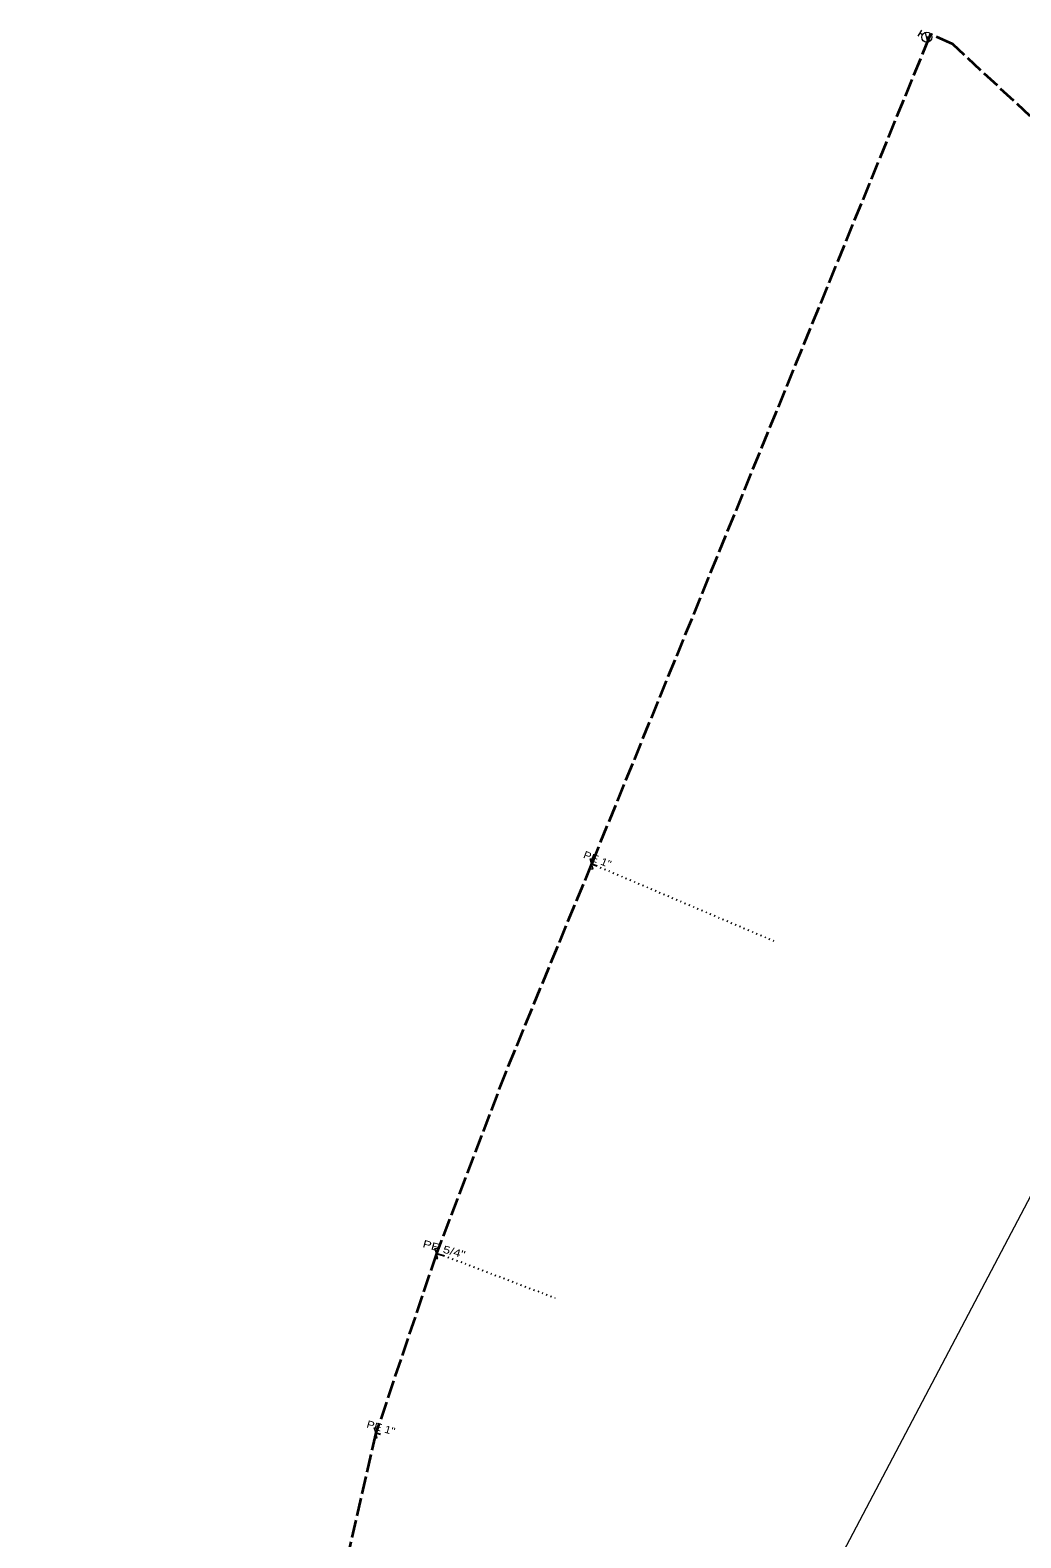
# Model space of a CAD drawing. Extents: x -582626 to -580899, y -1097611 to -1096610.
# Drawn here: x -581490.3 to -581390.7, y -1096761 to -1096609.6 of the extents above; entities that cross this region are included whole.
import ezdxf
from ezdxf.enums import TextEntityAlignment as Align

# ---------------------------------------------------------------- set-up
doc = ezdxf.new("R2010")
doc.units = 0
doc.header["$LTSCALE"] = 0.3
doc.linetypes.add('DOTTED', pattern=[1.5, 0.3, -1.2])
doc.linetypes.add('LONG_DASHED', pattern=[7.5, 6, -1.5])
for name, color, linetype, lineweight in [('1', 7, 'Continuous', 13), ('10', 7, 'Continuous', 13), ('35', 7, 'LONG_DASHED', 35), ('50', 7, 'LONG_DASHED', 25), ('51', 7, 'DOTTED', 25)]:
    doc.layers.add(name, color=color, linetype=linetype, lineweight=lineweight)
doc.layers.add('19', color=7, linetype='Continuous')

msp = doc.modelspace()

# ---------------------------------------------------------------- linework, layer by layer
at = {"layer": '1'}
msp.add_lwpolyline([(-582625.57, -1097394.66), (-582612.34, -1097467.421), (-582321.299, -1097262.369), (-581897.965, -1097202.837), (-581719.372, -1097182.994), (-581593.695, -1097110.233), (-581382.028, -1096971.327), (-581362.184, -1096819.192), (-581322.497, -1096739.817), (-581210.049, -1096733.202), (-581097.601, -1096686.9), (-580905.778, -1096719.973), (-580899.163, -1096627.369), (-581084.372, -1096614.14), (-581216.663, -1096680.285), (-581368.799, -1096686.9), (-581434.945, -1096812.577), (-581468.018, -1096971.327), (-581659.84, -1097004.4), (-581831.82, -1097110.233), (-582314.684, -1097169.765), (-582519.736, -1097295.442), (-582625.57, -1097394.66)], close=True, dxfattribs=at)
at = {"layer": '10'}
for p, q in [((-581401.014, -1096610.197), (-581400.652, -1096609.598)), ((-581400.576, -1096610.052), (-581400.833, -1096609.897)), ((-581400.028, -1096610.797), (-581400.268, -1096609.826))]:
    msp.add_line(p, q, dxfattribs=at)
for points in [[(-581433.835, -1096693.326), (-581433.985, -1096692.826), (-581433.685, -1096692.826), (-581433.835, -1096693.326), (-581433.985, -1096693.826), (-581433.685, -1096693.826)], [(-581449.419, -1096732.464), (-581449.569, -1096731.964), (-581449.269, -1096731.964), (-581449.419, -1096732.464), (-581449.569, -1096732.964), (-581449.269, -1096732.964)], [(-581455.523, -1096750.461), (-581455.673, -1096749.961), (-581455.373, -1096749.961), (-581455.523, -1096750.461), (-581455.673, -1096750.961), (-581455.373, -1096750.961)]]:
    msp.add_lwpolyline(points, close=True, dxfattribs=at)
msp.add_circle((-581400.1481, -1096610.3107), 0.5, dxfattribs=at)
at = {"layer": '35'}
msp.add_line((-581400.148, -1096610.311), (-581399.945, -1096610.388), dxfattribs=at)
for points in [[(-581399.786, -1096610.001), (-581399.945, -1096610.388), (-581433.835, -1096693.326)], [(-581338.976, -1096669.3), (-581341.123, -1096666.369), (-581373.277, -1096633.554), (-581397.534, -1096611.01), (-581399.786, -1096610.001)], [(-581433.835, -1096693.326), (-581442.496, -1096714.31), (-581449.419, -1096732.464)], [(-581449.419, -1096732.464), (-581455.402, -1096750.202), (-581455.523, -1096750.461)], [(-581455.523, -1096750.461), (-581465.398, -1096793.715), (-581467.375, -1096804.966), (-581469.14, -1096820.168), (-581469.913, -1096823.394)]]:
    msp.add_lwpolyline(points, dxfattribs=at)
at = {"layer": '50'}
for p, q in [((-581433.835, -1096693.326), (-581433.38, -1096693.503)), ((-581449.419, -1096732.464), (-581448.699, -1096732.662)), ((-581455.523, -1096750.461), (-581455.05, -1096750.596))]:
    msp.add_line(p, q, dxfattribs=at)
at = {"layer": '51'}
for p, q in [((-581433.38, -1096693.503), (-581415.534, -1096701.055)), ((-581448.699, -1096732.662), (-581437.508, -1096736.922))]:
    msp.add_line(p, q, dxfattribs=at)

# ---------------------------------------------------------------- texts
at = {"layer": '19'}
for s, rotation, width, p in [('PE 1"', 338.743, 1.15, (-581433.386, -1096693.2321)), ('PE 5/4"', 344.624, 1.3, (-581448.7549, -1096732.3872)), ('PE 1"', 344.071, 1.15, (-581455.1069, -1096750.3195))]:
    msp.add_text(s, height=0.75, rotation=rotation, dxfattribs=dict(at, width=width)).set_placement(p, align=Align.CENTER)

doc.saveas('drawing.dxf')
